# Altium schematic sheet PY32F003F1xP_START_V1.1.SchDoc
size A4
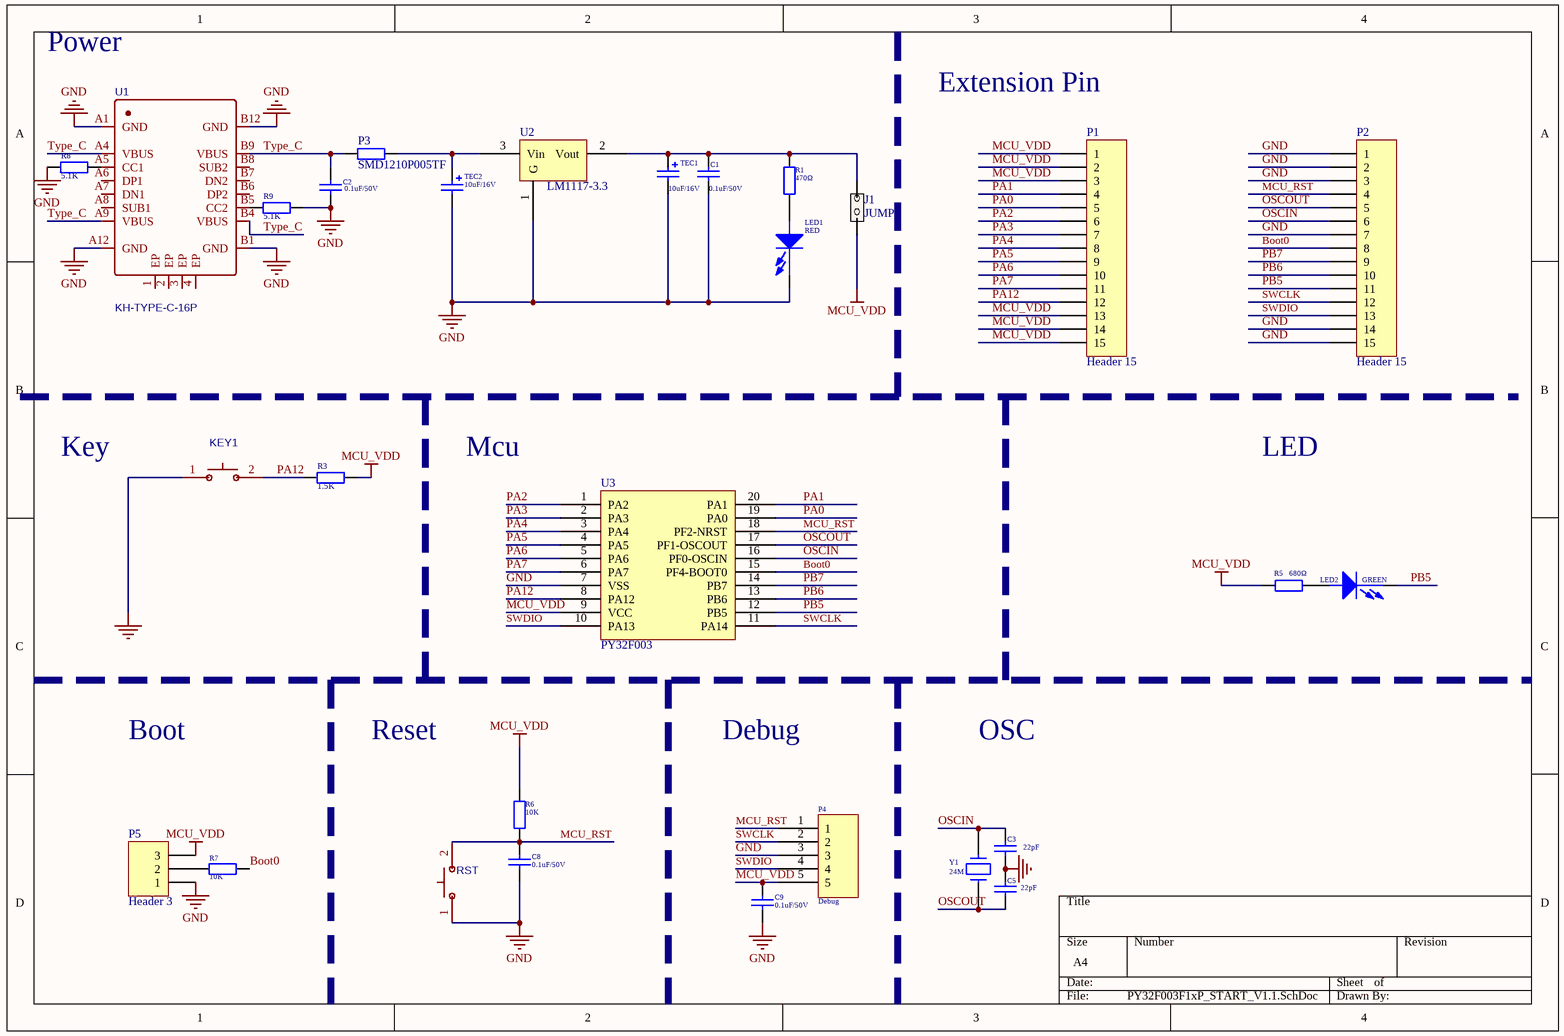
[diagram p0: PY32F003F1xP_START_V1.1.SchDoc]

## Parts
C1  0.1uF/50V  [0603C]
C2  0.1uF/50V  [0603C]
C3  22pF  [0603C]
C5  22pF  [0603C]
C8  0.1uF/50V  [0603C]
C9  0.1uF/50V  [0603C]
J1  JUMP  [HDR1X2]
KEY1  1TS002B-2600-5001  [SW]  (value not drawn)
LED1  RED  [0603_LED]
LED2  GREEN  [0603_LED]
P1  Header 15  [HDR1X15]
P2  Header 15  [HDR1X15]
P3  SMD1210P005TF  [SDM1210P005TF]
P4  Debug  [HDR1X5]
P5  Header 3  [HDR1X3]
R1  470Ω  [0603R]
R3  1.5K  [0603R]
R5  680Ω  [0603R]
R6  10K  [0603R]
R7  10K  [0603R]
R8  5.1K  [0603R]
R9  5.1K  [0603R]
RST  1TS002B-2600-5001  [SW]  (value not drawn)
TEC1  value 10uF/16V  [0603]  (hidden comment: 10uF)
TEC2  value 10uF/16V  [0603]  (hidden comment: 10uF)
U1  KH-TYPE-C-16P  [USB-C-SMD_KH-TYPE-C-16P]
U2  LM1117-3.3  [LM1117-3.3]
U3  PY32F003  [TSSOP20]
Y1  24M  [25MHZ_2]

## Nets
GND: C1.1 C2.1 C3.1 C5.2 C8.1 C9.1 KEY1.1(A) LED1.2(CATHODE) P2.1 P2.2 P2.3 P2.7 P2.14 P2.15 P4.3 P5.1 R8.1 R9.2 RST.1(A) TEC1.2 TEC2.2 U1.A1(GND) U1.A12(GND) U1.B1(GND) U1.B12(GND) U2.1(G) U3.7(VSS)
MCU_VDD: C9.2 J1.1 P1.1 P1.2 P1.3 P1.13 P1.14 P1.15 P4.5 P5.3 R3.2 R5.1 R6.2 U3.9(VCC)
Boot0: P2.8 R7.2 U3.15(PF4-BOOT0)
MCU_RST: C8.2 P2.4 P4.1 R6.1 RST.2(B) U3.18(PF2-NRST)
OSCIN: C3.2 P2.6 U3.16(PF0-OSCIN) Y1.1
OSCOUT: C5.1 P2.5 U3.17(PF1-OSCOUT) Y1.2
PA0: P1.5 U3.19(PA0)
PA1: P1.4 U3.20(PA1)
PA2: P1.6 U3.1(PA2)
PA3: P1.7 U3.2(PA3)
PA4: P1.8 U3.3(PA4)
PA5: P1.9 U3.4(PA5)
PA6: P1.10 U3.5(PA6)
PA7: P1.11 U3.6(PA7)
PA12: KEY1.2(B) P1.12 R3.1 U3.8(PA12)
PB5: LED2.2(CATHODE) P2.11 U3.12(PB5)
PB6: P2.10 U3.13(PB6)
PB7: P2.9 U3.14(PB7)
SWCLK: P2.12 P4.2 U3.11(PA14)
SWDIO: P2.13 P4.4 U3.10(PA13)
Type_C: C2.2 P3.1 U1.A4(VBUS) U1.A9(VBUS) U1.B4(VBUS) U1.B9(VBUS)
NetC1_2: C1.2 J1.2 R1.1 TEC1.1 U2.2(Vout)
NetLED1_1: LED1.1(ANODE) R1.2
NetLED2_1: LED2.1(ANODE) R5.2
NetP3_2: P3.2 TEC2.1 U2.3(Vin)
NetP5_2: P5.2 R7.1
NetR8_2: R8.2 U1.A5(CC1)
NetR9_1: R9.1 U1.B5(CC2)

Not connected (* = marked no-connect by the designer): U1 1(EP) 2(EP) 3(EP) 4(EP) A6(DP1) A7(DN1) A8(SUB1) B6(DP2) B7(DN2) B8(SUB2)

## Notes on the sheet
- Power
- Extension Pin
- Key
- Mcu
- LED
- Boot
- Reset
- Debug
- OSC

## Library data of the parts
C1 C3 C5 = Cap: Capacitor
C2 C8 C9 = CAP: Capacitor; Value: 2.2uF
KEY1 RST = 1TS002B-2600-5001: BOM_Manufacturer: HYP; Contributor: LCSC
LED1 LED2 = PDI-E803_Dup1
P1 P2 = Header 15: Header, 15-Pin
P4 = CON5
P5 = Header 3: Header, 3-Pin
R1 R3 R5 = Res: Resistor; 器件封装(外观): 0603; Value: 10K
R6 R7 = Res: Resistor; 器件封装(外观): 0603
R8 R9 = Res_1: Resistor; 器件封装(外观): 0603; Value: 10K
TEC1 TEC2 = 贴片钽电容: 器件封装(外观): 3528
U1 = KH-TYPE-C-16P: BOM_Manufacturer: Shenzhen Kinghelm Elec; Contributor: LCSC
U3 = Component_1
Y1 = CRYSTAL: Value: X503225MSB2GI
